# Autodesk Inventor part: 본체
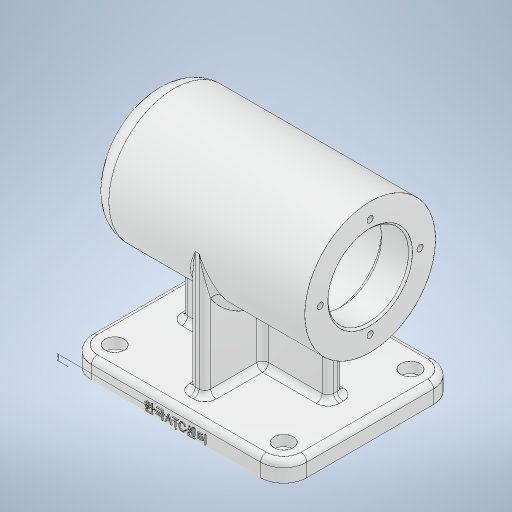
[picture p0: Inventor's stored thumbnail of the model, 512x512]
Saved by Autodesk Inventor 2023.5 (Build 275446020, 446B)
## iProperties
Created: 2026-08
Part Number: 본체
Material: 알루미늄 6061
Document SubType Name: Modeling
Designer: 1강의실14
Density: 2.7 g/cm^3
Appearance: 알루미늄 - 평지
Mass: 1025.89 g
Surface Area: 757.812 cm^2
Volume: 379.96 cm^3
Author: 1강의실14
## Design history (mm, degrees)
sketch "스케치1"
  geometry: L1 (56, 45)-(-56, 45); L2 (-56, 45)-(-56, -45); L3 (-56, -45)-(56, -45); L4 (56, -45)-(56, 45); L5 (56, 45)-(-56, -45); L6 (-56, 45)-(56, -45); 1 further point
  constraints: 12 end point, 2 midpoint, 2 parallel, 1 horizontal, 1 perpendicular
  dimensions: "d0" = 112 distance of L3.end L2.end; "d1" = 90 distance of L1.end L2.end
extrude "돌출1" new body sketch "스케치1" distance "d2" = 10; taper "d3" = 0 deg
sketch "스케치2"
  geometry: L1 (0, 0)-(0, 74); L2 (0, 74)-(44.651, 74); L3 (56, 0)-(-56, 0) reference; L4 (-46, 108)-(56, 108); L5 (56, 108)-(56, 96); L6 (55, 95)-(41, 95); L7 (41, 95)-(41, 95); L8 (38, 98)-(-10, 98); L9 (-13, 95)-(-13, 95); L10 (-13, 95)-(-24.4, 95); L11 (-25, 94.4)-(-25, 91.5); L12 (-25, 91.5)-(-43, 91.5); L13 (-43, 91.5)-(-43, 90); L14 (-43, 90)-(-46.4, 90); L15 (-50, 74)-(-56, 74); L16 (-56, 74)-(-56, 98); L17 (-47, 89.4)-(-47, 84.5); L18 (-47, 84.5)-(-47, 84.5); L19 (-50, 81.5)-(-50, 74); L20 (55, 95)-(56, 96); A1 r 0.6 centre (-46.4, 89.4) between (-46.4, 90) and (-47, 89.4); A2 r 0.6 centre (-24.4, 94.4) between (-24.4, 95) and (-25, 94.4); A3 r 10 centre (-46, 98) between (-46, 108) and (-56, 98); A4 r 3 centre (-10, 95) between (-10, 98) and (-13, 95); A5 r 3 centre (38, 95) between (41, 95) and (38, 98); A6 r 3 centre (-47, 81.5) between (-47, 84.5) and (-50, 81.5); 12 further points
  constraints: 38 end point, 16 point on line, 14 perpendicular, 12 point on circle, 12 tangent, 6 centre point, 2 collinear, 2 midpoint, 2 vertical, 1 equal radius, 1 horizontal
  dimensions: "d4" = 74 distance between parallel lines of L2 L3; "d5" = 112 distance of point (-56, 108) L4.end; "d6" = 54 distance of point (41, 98) point (-13, 98); "d7" = 15 distance of point (56, 95) L6.end; "d8" = 18 distance of L11.end L12.end; "d9" = 103 horizontal distance of point (56, 95) point (-47, 90); "d10" = 42 diameter of point (48, 95) L2; "d11" = 68 diameter of L4 L2; "d12" = 48 diameter of L8 L2; "d17" = 81 horizontal distance of L4.end point (-25, 95); "d18" = 3 distance of L17.end point (-50, 84.5); "d19" = 21 diameter of L18 L2; "d20" = 32 diameter of L14 L2; "d21" = 35 diameter of L12 L2; "d22" = 0.6 radius of A1; "d23" = 0.6 radius of A2 (derived); "d24" = 10 radius of A3 (derived); "d25" = 3 radius of A4; "d26" = 1 distance of L6.start point (56, 95); "d27" = 1 distance of L5.end point (56, 95) (= d26); "d28" = 3 radius of A6 (derived); "d64" = 56 distance between parallel lines of L1 L5
revolve "회전1" sketch "스케치2" stored, may be unused: angle "d29" = 90 deg
sketch "스케치3"
  geometry: L1 (56, -45)-(56, 45) reference; L2 (-56, -45)-(56, -45) reference; L3 (-56, 45)-(-56, -45) reference; L4 (56, 45)-(-56, 45) reference; L5 (0, 0)-(19.584, 0); L6 (0, 0)-(0, 15.112); 4 further points
  constraints: 4 end point, 2 symmetric about line, 1 horizontal, 1 vertical, 1 vertical alignment
  dimensions: "d30" = 66 distance of point (44, -33) point (44, 33); "d31" = 44 distance from line of L6 point (44, -33); "d32" = 33 distance from line of point (44, -33) L5
hole "구멍1" sketch "스케치3" at (44, 33), (44, -33), (-44, 33), (-44, -33) diameter "d33" = 5.5; stored, may be unused: countersink angle "d37" = 90 deg, drill point angle "d39" = 118 deg; dims "d34" = 9, "d35" = 10, "d36" = 5.5, "d38" = 11
fillet "모깎기1" dims "d40" = 12
sketch "스케치4"
  geometry: L1 (44, 45)-(-44, 45) reference; L2 (-56, 33)-(-56, -33) reference; L3 (-44, -45)-(44, -45) reference; L4 (56, -33)-(56, 33) reference; C1 r 5 at (-44, 33) reference; C2 r 5 at (44, 33) reference; C3 r 5 at (44, -33) reference; C4 r 5 at (-44, -33) reference; A1 r 12 centre (44, 33) between (56, 33) and (44, 45) reference; A2 r 12 centre (-44, 33) between (-44, 45) and (-56, 33) reference; A3 r 12 centre (-44, -33) between (-56, -33) and (-44, -45) reference; A4 r 12 centre (44, -33) between (44, -45) and (56, -33) reference; 1 further point
sketch "스케치5"
  geometry: L1 (-4, 34)-(4, 34); L2 (4, 34)-(4, -34); L3 (4, -34)-(-4, -34); L4 (-4, -34)-(-4, 34); L5 (-4, 34)-(4, -34); L6 (4, 34)-(-4, -34); L7 (-38, 4)-(38, 4); L8 (38, 4)-(38, -4); L9 (38, -4)-(-38, -4); L10 (-38, -4)-(-38, 4); L11 (-38, 4)-(38, -4); L12 (38, 4)-(-38, -4); 5 further points
  constraints: 24 end point, 4 midpoint, 4 parallel, 2 horizontal, 2 perpendicular
  dimensions: "d41" = 8 distance of L2.end L3.end; "d42" = 68 distance of L1.end L2.end; "d43" = 76 distance of L8.end L9.end; "d44" = 8 distance of L7.end L8.end
extrude "돌출2" join sketch "스케치5" stored distance "d45" = 10; taper "d46" = 0 deg
sketch "스케치6" dims "d47" = 52
  geometry: C1 r 34 at (0, 0) reference; C2 r 22 at (0, 0) reference; 6 further points
  constraints: 2 vertical alignment, 1 coincident, 7 other
  dimensions: "d50" = 360 deg dimension on C2.centre point (0, 26) (derived)
hole "구멍2" sketch "스케치6" at (0, 26), (-26, 0), (0, -26), (26, 0) diameter "d52" = 3.242; stored, may be unused: countersink angle "d56" = 90 deg, drill point angle "d58" = 118 deg; dims "d53" = 8, "d54" = 10, "d55" = 5.5, "d57" = 10
fillet "모깎기2" dims "d59" = 3
fillet "모깎기3" dims "d60" = 3
sketch "스케치7"
  geometry: L1 (0, 0)-(88, 0) reference; L2 (0, 0)-(-12, 0) reference; 4 further points
  constraints: 1 coincident, 1 midpoint, 1 vertical alignment, 1 other
  dimensions: "d61" = 3 distance from line of L2 point (44, 3)
feature "엠보싱1" dims "d0" = 112, "d1" = 90, "d8" = 18, "d62" = 0.5, "d63" = 0
feature "˲耀˴耀˶耀˸耀˺耀˼耀˾耀̀耀" dims "d0" = 112, "d1" = 90, "d2" = 10, "d3" = 0, "d4" = 74, "d5" = 112, "d6" = 54, "d7" = 15, "d8" = 18, "d9" = 103, "d10" = 42, "d11" = 68, "d12" = 48, "d17" = 81, "d18" = 3, "d19" = 21, "d20" = 32, "d21" = 35, "d22" = 0.6, "d23" = 0.6 (derived), "d24" = 10 (derived), "d25" = 3, "d26" = 1, "d27" = 1 (= d26)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
node "솔리드1"
node "투영된 루프1"
feature "A9D066F2-1C7D-4E18-AEED-F7BC21143FA4" dims "d33" = 5.5, "d34" = 9, "d35" = 10, "d36" = 5.5, "d37" = 90 deg, "d38" = 11, "d39" = 118 deg
